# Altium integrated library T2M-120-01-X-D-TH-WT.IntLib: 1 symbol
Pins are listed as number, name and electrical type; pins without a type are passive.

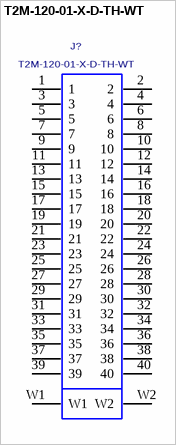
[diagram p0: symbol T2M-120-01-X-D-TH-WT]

## T2M-120-01-X-D-TH-WT
designator J?
2MM PITCH SHROUDED TERMINAL STRIP, 40 PINS.; MANUFACTURER: SAMTEC
footprint T2M-120-01-X-D-TH-WT
pins: 1, 2, 3, 4, 5, 6, 7, 8, 9, 10, 11, 12, 13, 14, 15, 16, 17, 18, 19, 20, 21, 22, 23, 24, 25, 26, 27, 28, 29, 30, 31, 32, 33, 34, 35, 36, 37, 38, 39, 40, W1, W2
